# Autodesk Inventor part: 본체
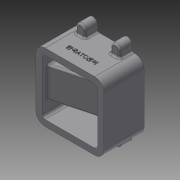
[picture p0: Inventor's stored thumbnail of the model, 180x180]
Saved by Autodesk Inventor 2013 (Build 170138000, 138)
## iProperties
Created: 2018-01
Part Number: 본체
Material: 일반
Document SubType Name: Modeling
Designer: Administrator
Density: 1 g/cm^3
Author: Administrator
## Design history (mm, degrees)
sketch "스케치1"
  geometry: L1 (55, -55)-(-55, -55); L2 (-55, -55)-(-55, 55); L3 (-55, 55)-(55, 55); L4 (55, 55)-(55, -55); 3 further points
  constraints: 8 end point, 2 midpoint, 2 parallel, 1 horizontal, 1 horizontal alignment, 1 perpendicular, 1 vertical alignment
  dimensions: "d0" = 110 distance of L1.start L1.end; "d2" = 110 distance of L3.end L1.start
extrude "돌출1" new body sketch "스케치1" distance "d3" = 65; taper "d4" = 0 deg
fillet "모깎기1" dims "d5" = 15
sketch "스케치3"
  geometry: L1 (40, 55)-(-40, 55) reference; L2 (-55, 40)-(-55, -40) reference; L3 (-40, -55)-(40, -55) reference; L4 (55, -40)-(55, 40) reference; L5 (-40, 45)-(40, 45); L6 (45, 40)-(45, -40); L7 (40, -45)-(-40, -45); L8 (-45, -40)-(-45, 40); A1 r 15 centre (40, 40) between (55, 40) and (40, 55) reference; A2 r 15 centre (-40, 40) between (-40, 55) and (-55, 40) reference; A3 r 15 centre (-40, -40) between (-55, -40) and (-40, -55) reference; A4 r 15 centre (40, -40) between (40, -55) and (55, -40) reference; A5 r 5 centre (40, 40) between (45, 40) and (40, 45); A6 r 5 centre (40, -40) between (40, -45) and (45, -40); A7 r 5 centre (-40, -40) between (-45, -40) and (-40, -45); A8 r 5 centre (-40, 40) between (-40, 45) and (-45, 40); 1 further point
  constraints: 8 end point, 8 point on circle, 4 centre point, 7 other
  dimensions: "d6" = 10 distance between parallel lines of L5 L1
extrude "돌출2" cut sketch "스케치3" stored distance "d7" = 65; taper "d8" = 0 deg
sketch "스케치10"
  geometry: L1 (-45, 65)-(35, 65); L2 (-45, 65)-(-45, 8.564); L3 (-45, 8.564)-(35, 30); L4 (35, 30)-(35, 65); L5 (-55, 0)-(-55, 65) reference; L6 (40, 0)-(-40, 0) reference; L7 (55, 65)-(55, 0) reference; 1 further point
  constraints: 8 end point, 1 horizontal, 1 parallel, 1 perpendicular
  dimensions: "d54" = 65 distance from line of L1 point (0, 0); "d55" = 10 distance between parallel lines of L2 L5; "d56" = 105 deg angle of L3 L5; "d57" = 30 distance from line of L3.end L6; "d58" = 20 distance between parallel lines of L4 L7
extrude "돌출4" join sketch "스케치10" stored distance "d59" = 50; taper "d60" = 0 deg
sketch "스케치11"
  geometry: L1 (-55, 40)-(-55, -40) reference; L2 (55, -40)-(55, 40) reference; L3 (-55, 7.5)-(-36, 7.5); L4 (-36, 7.5)-(-36, 16); L5 (-36, 16)-(-22, 16); L6 (-22, 16)-(-22, 20); L7 (-22, 20)-(25, 20); L8 (25, 20)-(25, 15); L9 (25, 15)-(30, 15); L10 (30, 15)-(30, 0); L11 (30, 0)-(-55, 0); L12 (-55, 7.5)-(-55, 0); 3 further points
  constraints: 20 end point, 6 parallel, 3 midpoint, 3 perpendicular, 2 collinear, 1 horizontal alignment
  dimensions: "d61" = 15 diameter of L3 L11; "d63" = 32 diameter of L5 L11; "d64" = 40 diameter of L7 L11; "d65" = 30 diameter of L9 L11; "d66" = 19 distance of L3.start L3.end; "d67" = 14 distance of L4.end L5.end; "d68" = 5 distance of L8.end L9.end; "d69" = 47 distance of L6.end L7.end
revolve "회전1" sketch "스케치11" stored, may be unused: angle "d70" = 90 deg
sketch "스케치15"
  geometry: L1 (20, -15)-(-17, -15); L2 (-17, -15)-(-17, 15); L3 (-22, 16)-(-22, 20) reference; L4 (-45, 25)-(-45, 40) reference; L5 (-17, 15)-(20, 15); L6 (20, 15)-(20, -15); 3 further points
  constraints: 8 end point, 2 horizontal alignment, 2 midpoint, 2 perpendicular
  dimensions: "d86" = 37 distance of L2.end L5.end; "d88" = 30 distance of L5.end L1.start; "d89" = 5 distance between parallel lines of L2 L3
extrude "돌출6" cut sketch "스케치15" distance "d84" = 30; taper "d85" = 0 deg
sketch "스케치13"
  geometry: L1 (-17, 45)-(-17, 39.878); L2 (-17, 39.878)-(-55, 29.696); L3 (-55, 11.061)-(20, 31.157); L4 (20, 31.157)-(20, 45); L5 (-55, 0)-(-55, 65) reference; L6 (35, 30)-(-45, 8.564) reference; L7 (-22, 65)-(-22, 45) reference; L8 (25, 65)-(25, 45) reference; L9 (-17, 45)-(20, 45); L10 (25, 45)-(-22, 45) reference; L11 (-55, 29.696)-(-55, 11.061); 1 further point
  constraints: 12 end point, 3 parallel, 2 perpendicular, 2 point on line, 1 collinear, 1 vertical
  dimensions: "d74" = 18 distance between parallel lines of L3 L2; "d75" = 5 distance between parallel lines of L3 L6; "d76" = 37 distance between parallel lines of L4 L1; "d77" = 5 distance between parallel lines of L1 L7
extrude "돌출5" cut sketch "스케치13" stored distance "d79" = 30; taper "d80" = 0 deg
sketch "스케치17"
  geometry: L1 (40, 55)-(-40, 55) reference; L2 (-55, 40)-(-55, 7.5) reference; L3 (-45, 25)-(-45, 40) reference; L4 (-35.5, 55)-(-35.5, 65); L5 (-20.5, 65)-(-20.5, 55); L6 (-35.5, 55)-(-20.5, 55); L7 (20.5, 55)-(20.5, 65); L8 (35.5, 65)-(35.5, 55); L9 (20.5, 55)-(35.5, 55); A1 r 7.5 centre (-28, 65) between (-20.5, 65) and (-35.5, 65); A2 r 7.5 centre (28, 65) between (35.5, 65) and (20.5, 65); 1 further point
  constraints: 12 end point, 4 point on circle, 4 point on line, 4 tangent, 2 centre point, 2 collinear, 2 parallel, 2 perpendicular
  dimensions: "d90" = 27 distance from line of A1.centre L2; "d91" = 7.5 radius of A1; "d92" = 10 distance from line of A1.centre L1; "d93" = 7.5 radius of A2; "d94" = 10 distance from line of L1 A2.centre; "d95" = 56 distance of A2.centre A1.centre
extrude "돌출7" join sketch "스케치17" distance "d96" = 20; taper "d97" = 0 deg
sketch "스케치18"
  geometry: A1 r 7.5 centre (28, 65) between (35.5, 65) and (20.5, 65) reference; A2 r 7.5 centre (-28, 65) between (-20.5, 65) and (-35.5, 65) reference; 3 further points
  constraints: 2 coincident
hole "구멍1" sketch "스케치18" at (-28, 65), (28, 65) diameter "d98" = 3.242; stored, may be unused: countersink angle "d102" = 90 deg, drill point angle "d104" = 118 deg; dims "d99" = 9, "d100" = 4, "d101" = 2, "d103" = 11
fillet "모깎기2" dims "d105" = 3
fillet "모깎기3" dims "d106" = 3
fillet "모깎기4" dims "d107" = 3
fillet "모깎기7" dims "d110" = 1
chamfer "모따기1" distance "d111" = 1; stored, may be unused: second distance "d112" = 2, angle "d113" = 45 deg
fillet "모깎기8" dims "d114" = 3
fillet "모깎기9" dims "d115" = 3
fillet "모깎기12" dims "d118" = 3
fillet "모깎기13" dims "d119" = 3
fillet "모깎기14" dims "d120" = 3
fillet "모깎기15" dims "d121" = 3
fillet "모깎기16" dims "d122" = 3
sketch "스케치19"
  geometry: L1 (80, 0)-(0, 0) reference; L2 (-15, 65)-(-15, 0) reference; 2 further points
  constraints: 1 other
  dimensions: "d123" = 20 distance from line of point (40, 20) L1; "d124" = 55 distance from line of point (40, 20) L2
feature "엠보싱1" sketch "스케치19" dims "d0" = 110, "d2" = 110, "d125" = 0.5, "d126" = 0
node "솔리드1"
mirror "대칭1"
